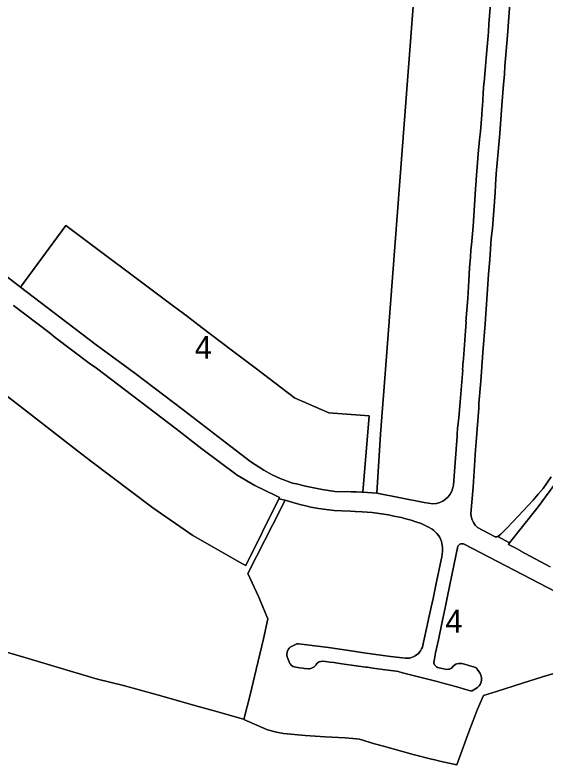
# Model space of a CAD drawing. Extents: x 598968 to 613553, y 4409678 to 4430833.
# Drawn here: x 600994.2 to 601272.5, y 4413927.6 to 4414320.9 of the extents above; entities that cross this region are included whole.
import ezdxf

# ---------------------------------------------------------------- set-up
doc = ezdxf.new("R2010")
doc.units = 0
for name, color, linetype in [('1', 7, 'Continuous'), ('Sòl Rústic Comú', 7, 'Continuous'), ('ZONA 4. CASES UNIFAMILIRAS AÏLLADES EN PARCEL.LES', 7, 'Continuous')]:
    doc.layers.add(name, color=color, linetype=linetype)

msp = doc.modelspace()

# ---------------------------------------------------------------- linework, layer by layer
at = {"layer": '1'}
for points in [[(600976.8333, 4414193.732), (600997.0529, 4414178.0823), (601020.8526, 4414210.5223), (601075.9411, 4414169.2649), (601080.5228, 4414165.8336), (601081.8294, 4414164.8377), (601084.647, 4414162.6902), (601092.3523, 4414156.8659), (601096.7208, 4414153.5637), (601108.227, 4414144.8396), (601120.8054, 4414135.3106), (601140.7532, 4414120.1102), (601141.0072, 4414119.9155), (601158.6602, 4414112.1945), (601179.8198, 4414110.7647), (601176.4198, 4414070.725), (601183.8497, 4414070.0751), (601185.6997, 4414101.1349), (601188.4669, 4414137.1786), (601198.1697, 4414263.5637), (601207.6196, 4414387.2328)], [(601243.5089, 4414329.2636), (601242.5189, 4414316.0937), (601242.3189, 4414312.2738), (601242.1089, 4414309.7838), (601241.9789, 4414308.2638), (601241.0389, 4414298.1539), (601240.6989, 4414294.0739), (601239.9889, 4414285.524), (601239.9389, 4414284.904), (601239.5389, 4414279.924), (601239.1189, 4414272.794), (601239.0661, 4414271.9748), (601238.8789, 4414268.5941), (601238.0489, 4414259.8541), (601237.629, 4414255.6342), (601236.969, 4414248.0542), (601235.879, 4414234.3743), (601235.789, 4414233.7343), (601235.549, 4414229.7543), (601234.219, 4414209.9245), (601233.429, 4414200.3246), (601233.069, 4414197.7746), (601232.839, 4414193.8146), (601232.349, 4414188.2747), (601231.959, 4414181.5747), (601231.479, 4414172.1548), (601230.449, 4414159.9249), (601230.6086, 4414159.9109), (601230.279, 4414155.3049), (601229.179, 4414140.535), (601228.9493, 4414137.5808), (601228.819, 4414136.935), (601228.7012, 4414134.8155), (601228.889, 4414134.8051), (601227.4395, 4414118.0627), (601226.729, 4414109.8552), (601226.3291, 4414105.2553), (601226.0991, 4414104.4753), (601225.8694, 4414100.88), (601225.8591, 4414100.0953), (601224.8691, 4414086.2154), (601224.0291, 4414074.3155), (601223.7191, 4414072.9155), (601223.116, 4414071.2305), (601222.2546, 4414069.6617), (601221.1564, 4414068.2486), (601219.849, 4414067.0265), (601218.365, 4414066.0259), (601216.7419, 4414065.2721), (601215.0201, 4414064.7839), (601213.2428, 4414064.5735), (601208.6677, 4414065.172), (601183.8497, 4414070.0751), (601176.4198, 4414070.725), (601175.9175, 4414070.7342), (601173.1935, 4414070.7841), (601170.4099, 4414070.835), (601161.8201, 4414071.0149), (601155.0802, 4414072.0148), (601146.4503, 4414073.8147), (601141.7014, 4414075.0502), (601139.5604, 4414075.4446), (601133.0806, 4414077.8245), (601128.9006, 4414079.7544), (601124.5207, 4414082.1344), (601117.8637, 4414086.521), (601107.2618, 4414094.559), (601082.2568, 4414113.8864), (601056.9319, 4414133.0733), (601036.6495, 4414147.9941), (601017.618, 4414162.4051), (600997.0529, 4414178.0823), (600976.8333, 4414193.732)], [(601274.6581, 4414031.5663), (601259.2684, 4414039.676), (601258.8584, 4414040.086), (601256.3785, 4414041.406), (601252.8288, 4414043.1972), (601252.9585, 4414043.5159), (601253.355, 4414044.0201), (601247.2586, 4414047.3458), (601246.8086, 4414047.2358), (601246.3386, 4414047.2058), (601245.8786, 4414047.2458), (601245.4286, 4414047.3558), (601236.5688, 4414052.0657), (601235.4022, 4414053.2932), (601234.4474, 4414054.6917), (601233.7289, 4414056.225), (601233.2655, 4414057.8537), (601233.0689, 4414059.5356), (601234.2088, 4414073.2756), (601235.5588, 4414092.8755), (601235.8088, 4414096.9954), (601237.1788, 4414114.7953), (601237.2588, 4414117.0853), (601238.3088, 4414128.8652), (601239.4188, 4414143.8451), (601240.5888, 4414158.925), (601241.6979, 4414174.5138), (601242.3188, 4414184.9448), (601242.9543, 4414192.7323), (601243.7588, 4414203.5947), (601244.3988, 4414209.0846), (601245.7788, 4414227.6645), (601246.0388, 4414231.8544), (601246.4288, 4414237.6144), (601246.7588, 4414241.4944), (601248.2988, 4414258.7942), (601249.3788, 4414273.5341), (601250.2588, 4414284.3841), (601250.6388, 4414289.854), (601250.8888, 4414294.064), (601252.2288, 4414310.0739), (601253.6387, 4414329.4837)], [(600993.413, 4414168.6023), (601012.0426, 4414154.4626), (601015.3226, 4414151.7427), (601033.1023, 4414138.363), (601036.9622, 4414135.653), (601078.6415, 4414103.9137), (601092.0612, 4414093.434), (601110.6409, 4414079.5143), (601119.8319, 4414074.0927), (601130.7602, 4414068.9238), (601132.8405, 4414067.9346), (601132.442, 4414067.1307), (601135.7405, 4414066.5346), (601141.0504, 4414064.9346), (601144.2383, 4414064.0938), (601146.6703, 4414063.4947), (601149.3003, 4414062.8547), (601153.1902, 4414062.0947), (601157.2817, 4414061.6164), (601161.4001, 4414061.1348), (601165.3902, 4414060.9044), (601169.9275, 4414060.6631), (601172.5092, 4414060.5569), (601176.1798, 4414060.405), (601181.3097, 4414059.9651), (601187.4496, 4414059.1851), (601189.8796, 4414058.7452), (601192.7722, 4414058.1472), (601196.7295, 4414057.3052), (601198.2895, 4414056.9453), (601201.8194, 4414055.9153), (601204.1994, 4414055.1253), (601207.0193, 4414054.1954), (601208.1581, 4414053.6655), (601211.3051, 4414052.2011), (601212.5292, 4414051.4954), (601212.7811, 4414051.3262), (601213.7201, 4414050.6161), (601214.6392, 4414049.7755), (601215.2992, 4414049.0455), (601216.2445, 4414047.7412), (601216.7534, 4414046.8705), (601217.3191, 4414045.6855), (601217.6491, 4414044.7656), (601217.9191, 4414043.8156), (601218.1091, 4414042.8556), (601218.2291, 4414041.8856), (601218.2991, 4414040.8156), (601218.2291, 4414039.5956), (601217.8291, 4414036.8156), (601217.4617, 4414035.1153), (601215.0536, 4414023.656), (601213.2434, 4414014.9794), (601212.2792, 4414010.3158), (601210.8492, 4414004.0058), (601210.1787, 4414000.8219), (601209.51, 4413997.6464), (601208.9724, 4413995.0937), (601208.2456, 4413991.9394), (601207.6592, 4413989.4059), (601207.2493, 4413988.4559), (601206.7393, 4413987.5559), (601206.1193, 4413986.7259), (601205.4093, 4413985.9759), (601204.6193, 4413985.3059), (601203.8318, 4413984.7839), (601202.8293, 4413984.2759), (601201.9421, 4413983.9466), (601200.8593, 4413983.6759), (601199.8294, 4413983.5558), (601198.7994, 4413983.5558), (601190.9622, 4413984.5314), (601176.9597, 4413986.4756), (601170.409, 4413987.5585), (601158.457, 4413989.2781), (601145.7202, 4413990.7852), (601142.7703, 4413991.1152), (601141.8774, 4413991.1933), (601138.3901, 4413989.3984), (601137.9204, 4413988.7952), (601137.4204, 4413988.1152), (601136.8804, 4413986.9052), (601136.7762, 4413986.3902), (601136.7062, 4413985.9726), (601136.6704, 4413985.1752), (601136.7704, 4413984.3952), (601138.2804, 4413980.9152), (601138.5704, 4413980.4052), (601139.1703, 4413979.7452), (601139.9203, 4413979.2552), (601140.4703, 4413979.0453), (601143.2693, 4413978.6127), (601144.9457, 4413978.3582), (601145.8882, 4413978.2694), (601147.9502, 4413978.0753), (601148.5002, 4413978.1153), (601149.5602, 4413978.3754), (601150.5502, 4413978.8454), (601151.0002, 4413979.1554), (601151.8001, 4413979.8954), (601152.0934, 4413980.3145), (601152.4301, 4413980.7954), (601152.7901, 4413981.2154), (601153.6601, 4413981.7254), (601154.3801, 4413981.9554), (601155.1401, 4413982.0454), (601156.8601, 4413981.8954), (601159.18, 4413981.6254), (601161.35, 4413981.3655), (601165.4399, 4413980.7355), (601172.8998, 4413979.6556), (601178.0997, 4413978.9657), (601178.6997, 4413978.9057), (601181.7797, 4413978.4657), (601186.9592, 4413977.7718), (601191.0941, 4413977.2177), (601193.8695, 4413976.8458), (601194.918, 4413976.6559), (601197.3094, 4413976.0159), (601202.8393, 4413974.4859), (601209.786, 4413972.7541), (601215.3453, 4413971.3681), (601217.8516, 4413970.7315), (601223.1827, 4413969.2501), (601226.9389, 4413968.2063), (601229.2889, 4413967.5763), (601233.3992, 4413966.4019), (601233.4588, 4413966.6063), (601233.7688, 4413966.5163), (601236.5687, 4413968.1764), (601236.9574, 4413968.5784), (601237.4487, 4413969.0864), (601237.9187, 4413969.7964), (601238.4087, 4413970.9664), (601238.6387, 4413972.2163), (601238.6787, 4413973.0963), (601238.4887, 4413974.3963), (601237.9887, 4413975.6163), (601237.2287, 4413976.6863), (601236.4287, 4413977.8963), (601235.8587, 4413978.5263), (601234.5588, 4413979.0762), (601233.8167, 4413979.3063), (601231.9788, 4413979.8762), (601229.7505, 4413980.4593), (601228.4237, 4413980.8007), (601227.4844, 4413980.9277), (601226.7689, 4413980.8962), (601225.7789, 4413980.6761), (601225.1745, 4413980.4127), (601224.449, 4413979.9561), (601223.8656, 4413979.4111), (601223.119, 4413978.6361), (601222.659, 4413978.2361), (601221.969, 4413977.9161), (601221.2948, 4413977.8248), (601220.439, 4413977.7761), (601215.5691, 4413978.766), (601215.109, 4413979.0319), (601214.6993, 4413979.3702), (601214.3513, 4413979.7718), (601214.0745, 4413980.2253), (601213.8766, 4413980.7185), (601213.763, 4413981.2376), (601213.737, 4413981.7683), (601213.7991, 4413982.296), (601214.6339, 4413986.4069), (601216.054, 4413993.3031), (601218.0551, 4414002.6776), (601219.7991, 4414010.9358), (601220.9191, 4414016.0958), (601224.2447, 4414032.2767), (601226.319, 4414042.2757), (601226.5067, 4414042.6023), (601226.7442, 4414042.8946), (601227.0255, 4414043.1451), (601227.3433, 4414043.3473), (601227.6894, 4414043.4961), (601228.0548, 4414043.5875), (601228.4301, 4414043.6192), (601228.8057, 4414043.5903), (601229.1717, 4414043.5018), (601229.5189, 4414043.3557), (601290.7356, 4414011.5929)], [(600977.4959, 4413990.197), (600994.6554, 4413985.4574), (601007.5749, 4413981.4978), (601025.0144, 4413976.3282), (601037.454, 4413972.6186), (601051.1135, 4413969.3089), (601071.2632, 4413963.6854), (601088.8962, 4413958.7198), (601098.5544, 4413956.0001), (601113.9014, 4413951.5805), (601114.1341, 4413951.4784), (601117.6133, 4413965.078), (601119.774, 4413974.0062), (601124.3878, 4413993.8392), (601126.6306, 4414004.1749), (601121.8407, 4414015.9148), (601116.1808, 4414027.9846), (601120.6931, 4414036.8856), (601129.2657, 4414053.7963), (601135.7405, 4414066.5346), (601132.442, 4414067.1307), (601115.159, 4414032.2743), (601113.4749, 4414033.0672), (601087.4613, 4414047.8942), (601066.4003, 4414062.378), (601033.7612, 4414087.1667), (601031.5031, 4414088.9186), (601027.0191, 4414092.318), (600998.6344, 4414114.3735), (600984.7168, 4414125.0986)], [(601275.1682, 4414078.656), (601271.0182, 4414072.676), (601268.3933, 4414069.566), (601265.7683, 4414066.4559), (601255.2052, 4414055.3025), (601251.9485, 4414051.8159), (601248.8186, 4414048.5859), (601247.2586, 4414047.3458), (601253.355, 4414044.0201), (601268.2883, 4414062.9559), (601276.5082, 4414074.236)]]:
    msp.add_lwpolyline(points, dxfattribs=at)
at = {"layer": 'Sòl Rústic Comú'}
msp.add_lwpolyline([(601280.816, 4413976.8136), (601270.5564, 4413973.8234), (601260.1267, 4413970.5632), (601246.5971, 4413966.093), (601239.7274, 4413964.013), (601236.5274, 4413956.943), (601231.9902, 4413944.9349), (601225.7378, 4413927.6232), (601216.7956, 4413929.6646), (601214.2182, 4413930.253), (601212.4795, 4413930.6799), (601202.8585, 4413933.0426), (601191.6189, 4413936.3324), (601187.279, 4413937.5022), (601182.6292, 4413938.7522), (601174.7394, 4413941.152), (601173.2395, 4413941.4219), (601167.1697, 4413941.8118), (601156.7, 4413942.3716), (601146.1804, 4413943.1713), (601134.9207, 4413944.101), (601131.2608, 4413944.831), (601126.451, 4413946.0708), (601114.1341, 4413951.4784), (601113.9014, 4413951.5805), (601098.5544, 4413956.0001), (601088.8962, 4413958.7198), (601071.2632, 4413963.6854), (601051.1135, 4413969.3089), (601037.454, 4413972.6186), (601025.0144, 4413976.3282), (601007.5749, 4413981.4978), (600994.6554, 4413985.4574), (600977.4959, 4413990.197)], dxfattribs=at)
at = {"layer": 'ZONA 4. CASES UNIFAMILIRAS AÏLLADES EN PARCEL.LES'}
for points in [[(601207.6196, 4414387.2328), (601198.1697, 4414263.5637), (601188.4669, 4414137.1786), (601185.6997, 4414101.1349), (601183.8497, 4414070.0751), (601208.6677, 4414065.172), (601213.2428, 4414064.5735), (601215.0201, 4414064.7839), (601216.7419, 4414065.2721), (601218.365, 4414066.0259), (601219.849, 4414067.0265), (601221.1564, 4414068.2486), (601222.2546, 4414069.6617), (601223.116, 4414071.2305), (601223.7191, 4414072.9155), (601224.0291, 4414074.3155), (601224.8691, 4414086.2154), (601225.8591, 4414100.0953), (601225.8694, 4414100.88), (601226.0991, 4414104.4753), (601226.3291, 4414105.2553), (601226.729, 4414109.8552), (601227.4395, 4414118.0627), (601228.889, 4414134.8051), (601228.7012, 4414134.8155), (601228.819, 4414136.935), (601228.9493, 4414137.5808), (601229.179, 4414140.535), (601230.279, 4414155.3049), (601230.6086, 4414159.9109), (601230.449, 4414159.9249), (601231.479, 4414172.1548), (601231.959, 4414181.5747), (601232.349, 4414188.2747), (601232.839, 4414193.8146), (601233.069, 4414197.7746), (601233.429, 4414200.3246), (601234.219, 4414209.9245), (601235.549, 4414229.7543), (601235.789, 4414233.7343), (601235.879, 4414234.3743), (601236.969, 4414248.0542), (601237.629, 4414255.6342), (601238.0489, 4414259.8541), (601238.8789, 4414268.5941), (601239.0661, 4414271.9748), (601239.1189, 4414272.794), (601239.5389, 4414279.924), (601239.9389, 4414284.904), (601239.9889, 4414285.524), (601240.6989, 4414294.0739), (601241.0389, 4414298.1539), (601241.9789, 4414308.2638), (601242.1089, 4414309.7838), (601242.3189, 4414312.2738), (601242.5189, 4414316.0937), (601243.5089, 4414329.2636)], [(601253.6387, 4414329.4837), (601252.2288, 4414310.0739), (601250.8888, 4414294.064), (601250.6388, 4414289.854), (601250.2588, 4414284.3841), (601249.3788, 4414273.5341), (601248.2988, 4414258.7942), (601246.7588, 4414241.4944), (601246.4288, 4414237.6144), (601246.0388, 4414231.8544), (601245.7788, 4414227.6645), (601244.3988, 4414209.0846), (601243.7588, 4414203.5947), (601242.9543, 4414192.7323), (601242.3188, 4414184.9448), (601241.6979, 4414174.5138), (601240.5888, 4414158.925), (601239.4188, 4414143.8451), (601238.3088, 4414128.8652), (601237.2588, 4414117.0853), (601237.1788, 4414114.7953), (601235.8088, 4414096.9954), (601235.5588, 4414092.8755), (601234.2088, 4414073.2756), (601233.0689, 4414059.5356), (601233.2655, 4414057.8537), (601233.7289, 4414056.225), (601234.4474, 4414054.6917), (601235.4022, 4414053.2932), (601236.5688, 4414052.0657), (601245.4286, 4414047.3558), (601245.8786, 4414047.2458), (601246.3386, 4414047.2058), (601246.8086, 4414047.2358), (601247.2586, 4414047.3458), (601248.8186, 4414048.5859), (601251.9485, 4414051.8159), (601255.2052, 4414055.3025), (601265.7683, 4414066.4559), (601268.3933, 4414069.566), (601271.0182, 4414072.676), (601275.1682, 4414078.656)], [(600984.7168, 4414125.0986), (600998.6344, 4414114.3735), (601027.0191, 4414092.318), (601031.5031, 4414088.9186), (601033.7612, 4414087.1667), (601066.4003, 4414062.378), (601087.4613, 4414047.8942), (601113.4749, 4414033.0672), (601115.159, 4414032.2743), (601132.442, 4414067.1307), (601132.8405, 4414067.9346), (601130.7602, 4414068.9238), (601119.8319, 4414074.0927), (601110.6409, 4414079.5143), (601092.0612, 4414093.434), (601078.6415, 4414103.9137), (601036.9622, 4414135.653), (601033.1023, 4414138.363), (601015.3226, 4414151.7427), (601012.0426, 4414154.4626), (600993.413, 4414168.6023)], [(601276.5082, 4414074.236), (601268.2883, 4414062.9559), (601253.355, 4414044.0201), (601252.9585, 4414043.5159), (601252.8288, 4414043.1972), (601256.3785, 4414041.406), (601258.8584, 4414040.086), (601259.2684, 4414039.676), (601274.6581, 4414031.5663)], [(601290.7356, 4414011.5929), (601229.5189, 4414043.3557), (601229.1717, 4414043.5018), (601228.8057, 4414043.5903), (601228.4301, 4414043.6192), (601228.0548, 4414043.5875), (601227.6894, 4414043.4961), (601227.3433, 4414043.3473), (601227.0255, 4414043.1451), (601226.7442, 4414042.8946), (601226.5067, 4414042.6023), (601226.319, 4414042.2757), (601224.2447, 4414032.2767), (601220.9191, 4414016.0958), (601219.7991, 4414010.9358), (601218.0551, 4414002.6776), (601216.054, 4413993.3031), (601214.6339, 4413986.4069), (601213.7991, 4413982.296), (601213.737, 4413981.7683), (601213.763, 4413981.2376), (601213.8766, 4413980.7185), (601214.0745, 4413980.2253), (601214.3513, 4413979.7718), (601214.6993, 4413979.3702), (601215.109, 4413979.0319), (601215.5691, 4413978.766), (601220.439, 4413977.7761), (601221.2948, 4413977.8248), (601221.969, 4413977.9161), (601222.659, 4413978.2361), (601223.119, 4413978.6361), (601223.8656, 4413979.4111), (601224.449, 4413979.9561), (601225.1745, 4413980.4127), (601225.7789, 4413980.6761), (601226.7689, 4413980.8962), (601227.4844, 4413980.9277), (601228.4237, 4413980.8007), (601229.7505, 4413980.4593), (601231.9788, 4413979.8762), (601233.8167, 4413979.3063), (601234.5588, 4413979.0762), (601235.8587, 4413978.5263), (601236.4287, 4413977.8963), (601237.2287, 4413976.6863), (601237.9887, 4413975.6163), (601238.4887, 4413974.3963), (601238.6787, 4413973.0963), (601238.6387, 4413972.2163), (601238.4087, 4413970.9664), (601237.9187, 4413969.7964), (601237.4487, 4413969.0864), (601236.9574, 4413968.5784), (601236.5687, 4413968.1764), (601233.7688, 4413966.5163), (601233.4588, 4413966.6063), (601233.3992, 4413966.4019), (601229.2889, 4413967.5763), (601226.9389, 4413968.2063), (601223.1827, 4413969.2501), (601217.8516, 4413970.7315), (601215.3453, 4413971.3681), (601209.786, 4413972.7541), (601202.8393, 4413974.4859), (601197.3094, 4413976.0159), (601194.918, 4413976.6559), (601193.8695, 4413976.8458), (601191.0941, 4413977.2177), (601186.9592, 4413977.7718), (601181.7797, 4413978.4657), (601178.6997, 4413978.9057), (601178.0997, 4413978.9657), (601172.8998, 4413979.6556), (601165.4399, 4413980.7355), (601161.35, 4413981.3655), (601159.18, 4413981.6254), (601156.8601, 4413981.8954), (601155.1401, 4413982.0454), (601154.3801, 4413981.9554), (601153.6601, 4413981.7254), (601152.7901, 4413981.2154), (601152.4301, 4413980.7954), (601152.0934, 4413980.3145), (601151.8001, 4413979.8954), (601151.0002, 4413979.1554), (601150.5502, 4413978.8454), (601149.5602, 4413978.3754), (601148.5002, 4413978.1153), (601147.9502, 4413978.0753), (601145.8882, 4413978.2694), (601144.9457, 4413978.3582), (601143.2693, 4413978.6127), (601140.4703, 4413979.0453), (601139.9203, 4413979.2552), (601139.1703, 4413979.7452), (601138.5704, 4413980.4052), (601138.2804, 4413980.9152), (601136.7704, 4413984.3952), (601136.6704, 4413985.1752), (601136.7062, 4413985.9726), (601136.7762, 4413986.3902), (601136.8804, 4413986.9052), (601137.4204, 4413988.1152), (601137.9204, 4413988.7952), (601138.3901, 4413989.3984), (601141.8774, 4413991.1933), (601142.7703, 4413991.1152), (601145.7202, 4413990.7852), (601158.457, 4413989.2781), (601170.409, 4413987.5585), (601176.9597, 4413986.4756), (601190.9622, 4413984.5314), (601198.7994, 4413983.5558), (601199.8294, 4413983.5558), (601200.8593, 4413983.6759), (601201.9421, 4413983.9466), (601202.8293, 4413984.2759), (601203.8318, 4413984.7839), (601204.6193, 4413985.3059), (601205.4093, 4413985.9759), (601206.1193, 4413986.7259), (601206.7393, 4413987.5559), (601207.2493, 4413988.4559), (601207.6592, 4413989.4059), (601208.2456, 4413991.9394), (601208.9724, 4413995.0937), (601209.51, 4413997.6464), (601210.1787, 4414000.8219), (601210.8492, 4414004.0058), (601212.2792, 4414010.3158), (601213.2434, 4414014.9794), (601215.0536, 4414023.656), (601217.4617, 4414035.1153), (601217.8291, 4414036.8156), (601218.2291, 4414039.5956), (601218.2991, 4414040.8156), (601218.2291, 4414041.8856), (601218.1091, 4414042.8556), (601217.9191, 4414043.8156), (601217.6491, 4414044.7656), (601217.3191, 4414045.6855), (601216.7534, 4414046.8705), (601216.2445, 4414047.7412), (601215.2992, 4414049.0455), (601214.6392, 4414049.7755), (601213.7201, 4414050.6161), (601212.7811, 4414051.3262), (601212.5292, 4414051.4954), (601211.3051, 4414052.2011), (601208.1581, 4414053.6655), (601207.0193, 4414054.1954), (601204.1994, 4414055.1253), (601201.8194, 4414055.9153), (601198.2895, 4414056.9453), (601196.7295, 4414057.3052), (601192.7722, 4414058.1472), (601189.8796, 4414058.7452), (601187.4496, 4414059.1851), (601181.3097, 4414059.9651), (601176.1798, 4414060.405), (601172.5092, 4414060.5569), (601169.9275, 4414060.6631), (601165.3902, 4414060.9044), (601161.4001, 4414061.1348), (601157.2817, 4414061.6164), (601153.1902, 4414062.0947), (601149.3003, 4414062.8547), (601146.6703, 4414063.4947), (601144.2383, 4414064.0938), (601141.0504, 4414064.9346), (601135.7405, 4414066.5346), (601129.2657, 4414053.7963), (601120.6931, 4414036.8856), (601116.1808, 4414027.9846), (601121.8407, 4414015.9148), (601126.6306, 4414004.1749), (601124.3878, 4413993.8392), (601119.774, 4413974.0062), (601117.6133, 4413965.078), (601114.1341, 4413951.4784), (601126.451, 4413946.0708), (601131.2608, 4413944.831), (601134.9207, 4413944.101), (601146.1804, 4413943.1713), (601156.7, 4413942.3716), (601167.1697, 4413941.8118), (601173.2395, 4413941.4219), (601174.7394, 4413941.152), (601182.6292, 4413938.7522), (601187.279, 4413937.5022), (601191.6189, 4413936.3324), (601202.8585, 4413933.0426), (601212.4795, 4413930.6799), (601214.2182, 4413930.253), (601216.7956, 4413929.6646), (601225.7378, 4413927.6232), (601231.9902, 4413944.9349), (601236.5274, 4413956.943), (601239.7274, 4413964.013), (601246.5971, 4413966.093), (601260.1267, 4413970.5632), (601270.5564, 4413973.8234), (601280.816, 4413976.8136)]]:
    msp.add_lwpolyline(points, dxfattribs=at)
msp.add_lwpolyline([(601176.4198, 4414070.725), (601179.8198, 4414110.7647), (601158.6602, 4414112.1945), (601141.0072, 4414119.9155), (601140.7532, 4414120.1102), (601120.8054, 4414135.3106), (601108.227, 4414144.8396), (601096.7208, 4414153.5637), (601092.3523, 4414156.8659), (601084.647, 4414162.6902), (601081.8294, 4414164.8377), (601080.5228, 4414165.8336), (601075.9411, 4414169.2649), (601020.8526, 4414210.5223), (600997.0529, 4414178.0823), (601017.618, 4414162.4051), (601036.6495, 4414147.9941), (601056.9319, 4414133.0733), (601082.2568, 4414113.8864), (601107.2618, 4414094.559), (601117.8637, 4414086.521), (601124.5207, 4414082.1344), (601128.9006, 4414079.7544), (601133.0806, 4414077.8245), (601139.5604, 4414075.4446), (601141.7014, 4414075.0502), (601146.4503, 4414073.8147), (601155.0802, 4414072.0148), (601161.8201, 4414071.0149), (601170.4099, 4414070.835), (601173.1935, 4414070.7841), (601175.9175, 4414070.7342)], close=True, dxfattribs=at)

# ---------------------------------------------------------------- texts
for p in [(601088.4363, 4414140.6236), (601219.7325, 4413997.0789)]:
    msp.add_text('4', height=12, dxfattribs=at).set_placement(p)

doc.saveas('drawing.dxf')
